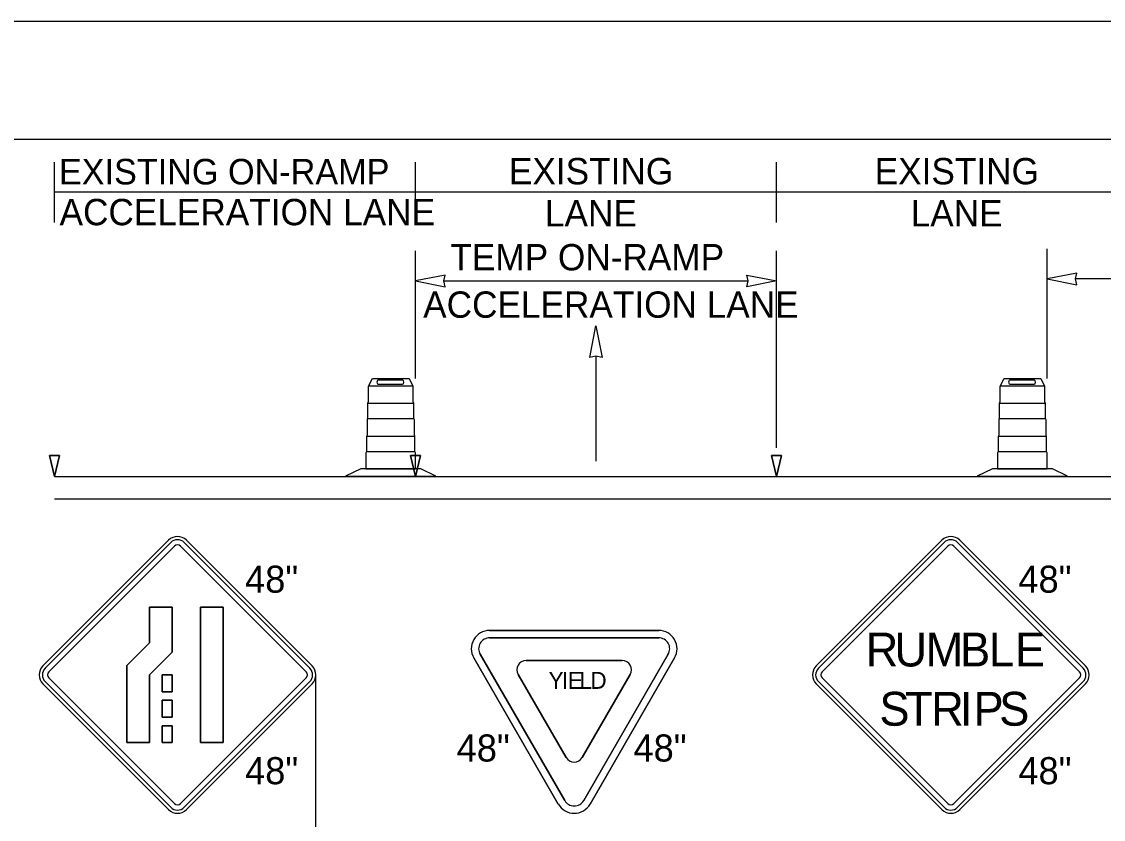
# Model space of a CAD drawing. Extents: x 99999 to 100116, y 99995 to 100013.
# Drawn here: x 100070.642 to 100073.519, y 100008.567 to 100010.687 of the extents above; entities that cross this region are included whole.
import ezdxf

# ---------------------------------------------------------------- set-up
doc = ezdxf.new("R2010")
doc.units = 0
for name, color, linetype in [('Default', 7, 'Continuous'), ('SH_GI_PlotLimits', 7, 'Continuous'), ('SH_GI_SheetBorder', 7, 'Continuous'), ('SH_TI_WZSectionCut', 7, 'Continuous'), ('TR_SN_ConstructionSigns', 7, 'Continuous'), ('TR_WZ_ArrowLeftStrRightTurn', 7, 'Continuous'), ('TR_WZ_TrafficSafetyDrumElev', 7, 'Continuous'), ('TR_WZ_WorkZoneDetails', 7, 'Continuous')]:
    doc.layers.add(name, color=color, linetype=linetype)

msp = doc.modelspace()

# ---------------------------------------------------------------- linework, layer by layer
at = {"layer": 'Default'}
for p, q in [((100071.0329, 100009.3089), (100070.6988, 100008.9747)), ((100071.4147, 100008.9747), (100071.0806, 100009.3089)), ((100073.0896, 100009.3089), (100072.7555, 100008.9747)), ((100073.4715, 100008.9747), (100073.1374, 100009.3089)), ((100070.6988, 100008.927), (100071.0329, 100008.5929)), ((100071.0806, 100008.5929), (100071.4147, 100008.927)), ((100072.7555, 100008.927), (100073.0896, 100008.5929)), ((100073.1374, 100008.5929), (100073.4715, 100008.927))]:
    msp.add_line(p, q, dxfattribs=at)
for centre, start, end in [((100071.0568, 100009.285), 45, 135), ((100073.1135, 100009.285), 45, 135), ((100070.7227, 100008.9509), 135, 225), ((100071.3909, 100008.9509), 315, 45), ((100072.7794, 100008.9509), 135, 225), ((100073.4476, 100008.9509), 315, 45), ((100071.0568, 100008.6168), 225, 315), ((100073.1135, 100008.6168), 225, 315)]:
    msp.add_arc(centre, 0.0338, start, end, dxfattribs=at)
at = {"layer": 'SH_GI_PlotLimits'}
msp.add_lwpolyline([(100059.0625, 99999.6875), (100076.0625, 99999.6875), (100076.0625, 100010.6875), (100059.0625, 100010.6875)], close=True, dxfattribs=at)
at = {"layer": 'SH_GI_SheetBorder'}
msp.add_line((100060, 100010.375), (100075.75, 100010.375), dxfattribs=at)
at = {"layer": 'SH_TI_WZSectionCut'}
for p, q in [((100073.3698, 100009.7388), (100073.3698, 100010.0836)), ((100074.2548, 100010.0036), (100073.4448, 100010.0036))]:
    msp.add_line(p, q, dxfattribs=at)
msp.add_lwpolyline([(100073.3698, 100010.0036), (100073.4484, 100009.9882), (100073.4448, 100010.0036), (100073.4484, 100010.019)], close=True, dxfattribs=at)
at = {"layer": 'TR_SN_ConstructionSigns'}
for p, q in [((100070.6988, 100008.9747), (100071.0329, 100009.3089)), ((100071.0389, 100009.3029), (100070.7048, 100008.9688)), ((100070.7147, 100008.9588), (100071.0488, 100009.2929)), ((100071.0647, 100009.2929), (100071.3988, 100008.9588)), ((100071.4088, 100008.9688), (100071.0747, 100009.3029)), ((100071.0806, 100009.3089), (100071.4147, 100008.9747)), ((100072.7555, 100008.9747), (100073.0896, 100009.3089)), ((100073.0956, 100009.3029), (100072.7615, 100008.9688)), ((100072.7714, 100008.9588), (100073.1055, 100009.2929)), ((100073.1215, 100009.2929), (100073.4556, 100008.9588)), ((100073.4655, 100008.9688), (100073.1314, 100009.3029)), ((100073.1374, 100009.3089), (100073.4715, 100008.9747)), ((100071.0427, 100009.1309), (100070.9822, 100009.1309)), ((100070.9822, 100009.1309), (100070.9822, 100009.0364)), ((100070.9822, 100009.0364), (100070.9822, 100009.1309)), ((100070.9822, 100009.1309), (100071.0427, 100009.1309)), ((100071.0427, 100009.0114), (100071.0427, 100009.1309)), ((100071.0427, 100009.1309), (100071.0427, 100009.0114)), ((100071.1784, 100009.1309), (100071.1179, 100009.1309)), ((100071.1179, 100009.1309), (100071.1179, 100008.7709)), ((100071.1179, 100008.7709), (100071.1179, 100009.1309)), ((100071.1179, 100009.1309), (100071.1784, 100009.1309)), ((100071.1784, 100008.7709), (100071.1784, 100009.1309)), ((100071.1784, 100009.1309), (100071.1784, 100008.7709)), ((100072.3367, 100009.069), (100071.887, 100009.069)), ((100070.9822, 100009.0364), (100070.9218, 100008.9759)), ((100070.9218, 100008.9759), (100070.9822, 100009.0364)), ((100071.887, 100009.0495), (100071.887, 100009.0497)), ((100071.887, 100009.0497), (100072.1119, 100009.0497)), ((100072.1119, 100009.0497), (100071.887, 100009.0497)), ((100071.887, 100009.0497), (100071.887, 100009.0495)), ((100070.9822, 100008.9509), (100071.0427, 100009.0114)), ((100071.0427, 100009.0114), (100070.9822, 100008.9509)), ((100072.0866, 100008.6171), (100071.8618, 100009.0057)), ((100071.8618, 100009.0057), (100072.0866, 100008.6171)), ((100072.362, 100009.0057), (100072.1372, 100008.6171)), ((100072.1372, 100008.6171), (100072.362, 100009.0057)), ((100070.9218, 100008.9759), (100070.9218, 100008.7709)), ((100070.9218, 100008.7709), (100070.9218, 100008.9759)), ((100072.0697, 100008.6073), (100071.8449, 100008.9959)), ((100071.8449, 100008.9959), (100072.0697, 100008.6073)), ((100072.1119, 100008.9888), (100071.9841, 100008.9888)), ((100071.9841, 100008.9888), (100072.1119, 100008.9888)), ((100072.2397, 100008.9888), (100072.1119, 100008.9888)), ((100072.1119, 100008.9888), (100072.2397, 100008.9888)), ((100072.3788, 100008.9959), (100072.154, 100008.6073)), ((100072.154, 100008.6073), (100072.3788, 100008.9959)), ((100070.9822, 100008.7709), (100070.9822, 100008.9509)), ((100070.9822, 100008.9509), (100070.9822, 100008.7709)), ((100071.0427, 100008.9509), (100071.016, 100008.9509)), ((100071.016, 100008.9509), (100071.016, 100008.9059)), ((100071.016, 100008.9059), (100071.016, 100008.9509)), ((100071.016, 100008.9509), (100071.0427, 100008.9509)), ((100071.0427, 100008.9059), (100071.0427, 100008.9509)), ((100071.0427, 100008.9509), (100071.0427, 100008.9059)), ((100071.963, 100008.9523), (100072.0908, 100008.7314)), ((100072.0908, 100008.7314), (100071.963, 100008.9523)), ((100072.1329, 100008.7314), (100072.2607, 100008.9523)), ((100072.2607, 100008.9523), (100072.1329, 100008.7314)), ((100071.0329, 100008.5929), (100070.6988, 100008.927)), ((100070.7048, 100008.933), (100071.0389, 100008.5989)), ((100071.0488, 100008.6088), (100070.7147, 100008.9429)), ((100071.3988, 100008.9429), (100071.0647, 100008.6088)), ((100071.0747, 100008.5989), (100071.4088, 100008.933)), ((100071.4147, 100008.927), (100071.0806, 100008.5929)), ((100073.0896, 100008.5929), (100072.7555, 100008.927)), ((100072.7615, 100008.933), (100073.0956, 100008.5989)), ((100073.1055, 100008.6088), (100072.7714, 100008.9429)), ((100073.4556, 100008.9429), (100073.1215, 100008.6088)), ((100073.1314, 100008.5989), (100073.4655, 100008.933)), ((100073.4715, 100008.927), (100073.1374, 100008.5929)), ((100071.016, 100008.9059), (100071.0427, 100008.9059)), ((100071.0427, 100008.9059), (100071.016, 100008.9059)), ((100071.0427, 100008.8834), (100071.016, 100008.8834)), ((100071.016, 100008.8834), (100071.016, 100008.8384)), ((100071.016, 100008.8384), (100071.016, 100008.8834)), ((100071.016, 100008.8834), (100071.0427, 100008.8834)), ((100071.0427, 100008.8384), (100071.0427, 100008.8834)), ((100071.0427, 100008.8834), (100071.0427, 100008.8384)), ((100071.016, 100008.8384), (100071.0427, 100008.8384)), ((100071.0427, 100008.8384), (100071.016, 100008.8384)), ((100071.0427, 100008.8159), (100071.016, 100008.8159)), ((100071.016, 100008.8159), (100071.016, 100008.7709)), ((100071.016, 100008.7709), (100071.016, 100008.8159)), ((100071.016, 100008.8159), (100071.0427, 100008.8159)), ((100071.0427, 100008.7709), (100071.0427, 100008.8159)), ((100071.0427, 100008.8159), (100071.0427, 100008.7709)), ((100070.9218, 100008.7709), (100070.9822, 100008.7709)), ((100070.9822, 100008.7709), (100070.9218, 100008.7709)), ((100071.016, 100008.7709), (100071.0427, 100008.7709)), ((100071.0427, 100008.7709), (100071.016, 100008.7709)), ((100071.1179, 100008.7709), (100071.1784, 100008.7709)), ((100071.1784, 100008.7709), (100071.1179, 100008.7709))]:
    msp.add_line(p, q, dxfattribs=at)
for points in [[(100071.887, 100009.069), (100072.3367, 100009.069)], [(100072.1119, 100009.0497), (100072.3367, 100009.0497), (100072.3367, 100009.0495)], [(100072.3367, 100009.0495), (100072.3367, 100009.0497), (100072.1119, 100009.0497)]]:
    msp.add_lwpolyline(points, dxfattribs=at)
for centre, radius, start, end in [((100071.0568, 100009.285), 0.0338, 45, 135), ((100073.1135, 100009.285), 0.0338, 45, 135), ((100071.0568, 100009.285), 0.0253, 45, 135), ((100071.0568, 100009.285), 0.0113, 45, 135), ((100073.1135, 100009.285), 0.0253, 45, 135), ((100073.1135, 100009.285), 0.0113, 45, 135), ((100071.887, 100009.0203), 0.0487, 90, 210.0517), ((100071.887, 100009.0203), 0.0487, 90, 210.0517), ((100072.3367, 100009.0203), 0.0487, 329.9522, 90), ((100072.3367, 100009.0203), 0.0487, 329.9522, 90), ((100071.887, 100009.0203), 0.0292, 90, 210.0517), ((100071.887, 100009.0203), 0.0292, 90, 210.0517), ((100072.3367, 100009.0203), 0.0292, 329.9522, 90), ((100072.3367, 100009.0203), 0.0292, 329.9522, 90), ((100070.7227, 100008.9509), 0.0338, 135, 225), ((100071.3909, 100008.9509), 0.0338, 315, 45), ((100071.9841, 100008.9645), 0.0244, 90, 210.0513), ((100071.9841, 100008.9645), 0.0244, 90, 210.0513), ((100072.2397, 100008.9645), 0.0244, 329.9514, 90), ((100072.2397, 100008.9645), 0.0244, 329.9514, 90), ((100072.7794, 100008.9509), 0.0338, 135, 225), ((100073.4476, 100008.9509), 0.0338, 315, 45), ((100070.7227, 100008.9509), 0.0253, 135, 225), ((100070.7227, 100008.9509), 0.0113, 135, 225), ((100071.3909, 100008.9509), 0.0113, 315, 45), ((100071.3909, 100008.9509), 0.0253, 315, 45), ((100072.7794, 100008.9509), 0.0253, 135, 225), ((100072.7794, 100008.9509), 0.0113, 135, 225), ((100073.4476, 100008.9509), 0.0113, 315, 45), ((100073.4476, 100008.9509), 0.0253, 315, 45), ((100072.1119, 100008.7436), 0.0244, 210.0519, 329.9525), ((100072.1119, 100008.7436), 0.0244, 210.0519, 329.9525), ((100071.0568, 100008.6168), 0.0253, 225, 315), ((100071.0568, 100008.6168), 0.0113, 225, 315), ((100072.1119, 100008.6317), 0.0487, 210.0518, 329.9516), ((100072.1119, 100008.6317), 0.0487, 210.0518, 329.9516), ((100072.1119, 100008.6317), 0.0292, 210.0518, 329.9516), ((100072.1119, 100008.6317), 0.0292, 210.0518, 329.9516), ((100073.1135, 100008.6168), 0.0253, 225, 315), ((100073.1135, 100008.6168), 0.0113, 225, 315), ((100071.0568, 100008.6168), 0.0338, 225, 315), ((100073.1135, 100008.6168), 0.0338, 225, 315)]:
    msp.add_arc(centre, radius, start, end, dxfattribs=at)
at = {"layer": 'TR_WZ_ArrowLeftStrRightTurn'}
msp.add_line((100072.1698, 100009.7986), (100072.1698, 100009.5187), dxfattribs=at)
msp.add_lwpolyline([(100072.1698, 100009.8787), (100072.1863, 100009.7947), (100072.1698, 100009.7986), (100072.1533, 100009.7947)], close=True, dxfattribs=at)
at = {"layer": 'TR_WZ_TrafficSafetyDrumElev'}
for p, q in [((100071.6555, 100009.734), (100071.5901, 100009.734)), ((100071.5901, 100009.7236), (100071.6555, 100009.7236)), ((100073.3355, 100009.734), (100073.2701, 100009.734)), ((100073.2701, 100009.7236), (100073.3355, 100009.7236)), ((100071.6831, 100009.7188), (100071.5647, 100009.7188)), ((100071.6831, 100009.7188), (100071.5647, 100009.7188)), ((100073.3631, 100009.7188), (100073.2447, 100009.7188)), ((100073.3631, 100009.7188), (100073.2447, 100009.7188)), ((100071.6854, 100009.6724), (100071.5624, 100009.6724)), ((100071.5624, 100009.6724), (100071.5624, 100009.6325)), ((100071.6854, 100009.6325), (100071.6854, 100009.6724)), ((100073.3654, 100009.6724), (100073.2424, 100009.6724)), ((100073.2424, 100009.6724), (100073.2424, 100009.6325)), ((100073.3654, 100009.6325), (100073.3654, 100009.6724)), ((100071.5624, 100009.6325), (100071.6854, 100009.6325)), ((100073.2424, 100009.6325), (100073.3654, 100009.6325)), ((100071.6883, 100009.5844), (100071.5595, 100009.5844)), ((100071.5595, 100009.5844), (100071.5595, 100009.5445)), ((100071.6883, 100009.5445), (100071.6883, 100009.5844)), ((100073.3683, 100009.5844), (100073.2395, 100009.5844)), ((100073.2395, 100009.5844), (100073.2395, 100009.5445)), ((100073.3683, 100009.5445), (100073.3683, 100009.5844)), ((100071.5595, 100009.5445), (100071.6883, 100009.5445)), ((100073.2395, 100009.5445), (100073.3683, 100009.5445))]:
    msp.add_line(p, q, dxfattribs=at)
for points in [[(100071.5647, 100009.7188), (100071.5752, 100009.7388), (100071.6726, 100009.7388), (100071.6831, 100009.7188)], [(100073.2447, 100009.7188), (100073.2552, 100009.7388), (100073.3526, 100009.7388), (100073.3631, 100009.7188)], [(100071.7439, 100009.4788), (100071.7037, 100009.4988), (100071.5441, 100009.4988), (100071.5039, 100009.4788)], [(100073.4239, 100009.4788), (100073.3837, 100009.4988), (100073.2241, 100009.4988), (100073.1839, 100009.4788)]]:
    msp.add_lwpolyline(points, close=True, dxfattribs=at)
for points in [[(100071.5639, 100009.7172), (100071.5639, 100009.676)], [(100071.5639, 100009.7172), (100071.5639, 100009.676)], [(100071.6839, 100009.676), (100071.6839, 100009.7172)], [(100071.6839, 100009.676), (100071.6839, 100009.7172)], [(100073.2439, 100009.7172), (100073.2439, 100009.676)], [(100073.2439, 100009.7172), (100073.2439, 100009.676)], [(100073.3639, 100009.676), (100073.3639, 100009.7172)], [(100073.3639, 100009.676), (100073.3639, 100009.7172)], [(100071.5624, 100009.673), (100071.5624, 100009.632)], [(100071.5624, 100009.673), (100071.5624, 100009.632)], [(100071.6854, 100009.632), (100071.6854, 100009.673)], [(100071.6854, 100009.632), (100071.6854, 100009.673)], [(100073.2424, 100009.673), (100073.2424, 100009.632)], [(100073.2424, 100009.673), (100073.2424, 100009.632)], [(100073.3654, 100009.632), (100073.3654, 100009.673)], [(100073.3654, 100009.632), (100073.3654, 100009.673)], [(100071.5609, 100009.629), (100071.5609, 100009.5879)], [(100071.5609, 100009.629), (100071.5609, 100009.5879)], [(100071.6869, 100009.5879), (100071.6869, 100009.629)], [(100071.6869, 100009.5879), (100071.6869, 100009.629)], [(100073.2409, 100009.629), (100073.2409, 100009.5879)], [(100073.2409, 100009.629), (100073.2409, 100009.5879)], [(100073.3669, 100009.5879), (100073.3669, 100009.629)], [(100073.3669, 100009.5879), (100073.3669, 100009.629)], [(100071.5595, 100009.5849), (100071.5595, 100009.5439)], [(100071.5595, 100009.5849), (100071.5595, 100009.5439)], [(100071.6883, 100009.5439), (100071.6883, 100009.5849)], [(100071.6883, 100009.5439), (100071.6883, 100009.5849)], [(100073.2395, 100009.5849), (100073.2395, 100009.5439)], [(100073.2395, 100009.5849), (100073.2395, 100009.5439)], [(100073.3683, 100009.5439), (100073.3683, 100009.5849)], [(100073.3683, 100009.5439), (100073.3683, 100009.5849)], [(100071.558, 100009.5409), (100071.558, 100009.4988), (100071.6898, 100009.4988), (100071.6898, 100009.5409)], [(100071.558, 100009.5409), (100071.558, 100009.4988), (100071.6898, 100009.4988), (100071.6898, 100009.5409)], [(100073.238, 100009.5409), (100073.238, 100009.4988), (100073.3698, 100009.4988), (100073.3698, 100009.5409)], [(100073.238, 100009.5409), (100073.238, 100009.4988), (100073.3698, 100009.4988), (100073.3698, 100009.5409)]]:
    msp.add_lwpolyline(points, dxfattribs=at)
for centre, major_axis, ratio, start_param, end_param in [((100071.5901, 100009.7288), (0, 0.0052), 0.570305, 6.283185, 9.424778), ((100071.6555, 100009.7288), (0, 0.0052), 0.570305, 3.141593, 6.283185), ((100073.2701, 100009.7288), (0, 0.0052), 0.570305, 6.283185, 9.424778), ((100073.3355, 100009.7288), (0, 0.0052), 0.570305, 3.141593, 6.283185), ((100071.5649, 100009.7168), (0, 0.00199), 0.493438, 0.177149, 1.393647), ((100071.5649, 100009.7168), (0, 0.00199), 0.493438, 0.177149, 1.393647), ((100071.6829, 100009.7168), (0, 0.00199), 0.493438, 4.889538, 6.106036), ((100071.6829, 100009.7168), (0, 0.00199), 0.493438, 4.889538, 6.106036), ((100073.2449, 100009.7168), (0, 0.00199), 0.493438, 0.177149, 1.393647), ((100073.2449, 100009.7168), (0, 0.00199), 0.493438, 0.177149, 1.393647), ((100073.3629, 100009.7168), (0, 0.00199), 0.493438, 4.889538, 6.106036), ((100073.3629, 100009.7168), (0, 0.00199), 0.493438, 4.889538, 6.106036), ((100071.5651, 100009.6705), (0, 0.00606), 0.493438, 0.4288, 1.141997), ((100071.5651, 100009.6705), (0, 0.00606), 0.493438, 0.4288, 1.141997), ((100071.6827, 100009.6705), (0, 0.00606), 0.493438, 5.141189, 5.854386), ((100071.6827, 100009.6705), (0, 0.00606), 0.493438, 5.141189, 5.854386), ((100073.2451, 100009.6705), (0, 0.00606), 0.493438, 0.4288, 1.141997), ((100073.2451, 100009.6705), (0, 0.00606), 0.493438, 0.4288, 1.141997), ((100073.3627, 100009.6705), (0, 0.00606), 0.493438, 5.141189, 5.854386), ((100073.3627, 100009.6705), (0, 0.00606), 0.493438, 5.141189, 5.854386), ((100071.5637, 100009.6265), (0, 0.00606), 0.493438, 0.4288, 1.141997), ((100071.5637, 100009.6265), (0, 0.00606), 0.493438, 0.4288, 1.141997), ((100071.6841, 100009.6265), (0, 0.00606), 0.493438, 5.141189, 5.854386), ((100071.6841, 100009.6265), (0, 0.00606), 0.493438, 5.141189, 5.854386), ((100073.2437, 100009.6265), (0, 0.00606), 0.493438, 0.4288, 1.141997), ((100073.2437, 100009.6265), (0, 0.00606), 0.493438, 0.4288, 1.141997), ((100073.3641, 100009.6265), (0, 0.00606), 0.493438, 5.141189, 5.854386), ((100073.3641, 100009.6265), (0, 0.00606), 0.493438, 5.141189, 5.854386), ((100071.5622, 100009.5824), (0, 0.00606), 0.493438, 0.4288, 1.141997), ((100071.5622, 100009.5824), (0, 0.00606), 0.493438, 0.4288, 1.141997), ((100071.6856, 100009.5824), (0, 0.00606), 0.493438, 5.141189, 5.854386), ((100071.6856, 100009.5824), (0, 0.00606), 0.493438, 5.141189, 5.854386), ((100073.2422, 100009.5824), (0, 0.00606), 0.493438, 0.4288, 1.141997), ((100073.2422, 100009.5824), (0, 0.00606), 0.493438, 0.4288, 1.141997), ((100073.3656, 100009.5824), (0, 0.00606), 0.493438, 5.141189, 5.854386), ((100073.3656, 100009.5824), (0, 0.00606), 0.493438, 5.141189, 5.854386), ((100071.5607, 100009.5384), (0, 0.00606), 0.493438, 0.4288, 1.141997), ((100071.5607, 100009.5384), (0, 0.00606), 0.493438, 0.4288, 1.141997), ((100071.6871, 100009.5384), (0, 0.00606), 0.493438, 5.141189, 5.854386), ((100071.6871, 100009.5384), (0, 0.00606), 0.493438, 5.141189, 5.854386), ((100073.2407, 100009.5384), (0, 0.00606), 0.493438, 0.4288, 1.141997), ((100073.2407, 100009.5384), (0, 0.00606), 0.493438, 0.4288, 1.141997), ((100073.3671, 100009.5384), (0, 0.00606), 0.493438, 5.141189, 5.854386), ((100073.3671, 100009.5384), (0, 0.00606), 0.493438, 5.141189, 5.854386)]:
    msp.add_ellipse(centre, major_axis=major_axis, ratio=ratio, start_param=start_param, end_param=end_param, dxfattribs=at)
at = {"layer": 'TR_WZ_WorkZoneDetails'}
for p, q in [((100070.7298, 100010.154), (100070.7298, 100010.314)), ((100071.6898, 100010.154), (100071.6898, 100010.314)), ((100072.6498, 100010.154), (100072.6498, 100010.314)), ((100071.6898, 100010.234), (100070.7298, 100010.234)), ((100072.6498, 100010.234), (100071.6898, 100010.234)), ((100073.6098, 100010.234), (100072.6498, 100010.234)), ((100071.6898, 100009.7388), (100071.6898, 100010.0783)), ((100072.6498, 100009.5546), (100072.6498, 100010.0783)), ((100071.7648, 100009.9983), (100072.5748, 100009.9983)), ((100070.7298, 100009.4787), (100074.4098, 100009.4787)), ((100070.7298, 100009.4187), (100074.4098, 100009.4187)), ((100071.4246, 100007.8308), (100071.4246, 100008.9509))]:
    msp.add_line(p, q, dxfattribs=at)
for points in [[(100071.6898, 100009.9983), (100071.7684, 100009.9829), (100071.7648, 100009.9983), (100071.7684, 100010.0137)], [(100072.6498, 100009.9983), (100072.5712, 100009.9829), (100072.5748, 100009.9983), (100072.5712, 100010.0137)], [(100070.7298, 100009.4787), (100070.7432, 100009.5346), (100070.7165, 100009.5346)], [(100071.6898, 100009.4787), (100071.7032, 100009.5346), (100071.6765, 100009.5346)], [(100072.6498, 100009.4787), (100072.6632, 100009.5346), (100072.6365, 100009.5346)]]:
    msp.add_lwpolyline(points, close=True, dxfattribs=at)
for points in [[(100070.7165, 100009.5346), (100070.7432, 100009.5346), (100070.7298, 100009.4787), (100070.7165, 100009.5346)], [(100071.6765, 100009.5346), (100071.7032, 100009.5346), (100071.6898, 100009.4787), (100071.6765, 100009.5346)], [(100072.6365, 100009.5346), (100072.6632, 100009.5346), (100072.6498, 100009.4787), (100072.6365, 100009.5346)]]:
    msp.add_lwpolyline(points, dxfattribs=at)

# ---------------------------------------------------------------- texts
at = {"layer": 'Default'}
for s, height, p in [('R', 0.09, (100072.8871, 100008.9734)), ('U', 0.09, (100072.9636, 100008.9734)), ('M', 0.09, (100073.0464, 100008.9734)), ('B', 0.09, (100073.1382, 100008.9734)), ('L', 0.09, (100073.2147, 100008.9734)), ('E', 0.09, (100073.284, 100008.9734)), ('Y', 0.045, (100072.0437, 100008.9139)), ('I', 0.045, (100072.0788, 100008.9139)), ('E', 0.045, (100072.095, 100008.9139)), ('L', 0.045, (100072.1256, 100008.9139)), ('D', 0.045, (100072.1548, 100008.9139)), ('S', 0.09, (100072.9236, 100008.8159)), ('T', 0.09, (100072.992, 100008.8159)), ('R', 0.09, (100073.0613, 100008.8159)), ('I', 0.09, (100073.1378, 100008.8159)), ('P', 0.09, (100073.1738, 100008.8159)), ('S', 0.09, (100073.2422, 100008.8159))]:
    msp.add_text(s, height=height, dxfattribs=at).set_placement(p)
at = {"layer": 'TR_SN_ConstructionSigns'}
for p in [(100071.2366, 100009.1694), (100073.2933, 100009.1694), (100071.7993, 100008.7206), (100072.2696, 100008.7206), (100071.2366, 100008.6603), (100073.2933, 100008.6603)]:
    msp.add_text('48"', height=0.072, dxfattribs=at).set_placement(p)
at = {"layer": 'TR_WZ_WorkZoneDetails'}
for s, height, p in [('EXISTING', 0.07, (100071.9383, 100010.255)), ('EXISTING', 0.07, (100072.911, 100010.255)), ('EXISTING ON-RAMP', 0.068, (100070.7415, 100010.2547)), ('ACCELERATION LANE', 0.07, (100070.7432, 100010.1463)), ('LANE', 0.07, (100072.034, 100010.143)), ('LANE', 0.07, (100073.0068, 100010.143)), ('TEMP ON-RAMP', 0.07, (100071.7826, 100010.0263)), ('ACCELERATION LANE', 0.07, (100071.7102, 100009.9003))]:
    msp.add_text(s, height=height, dxfattribs=at).set_placement(p)

doc.saveas('drawing.dxf')
